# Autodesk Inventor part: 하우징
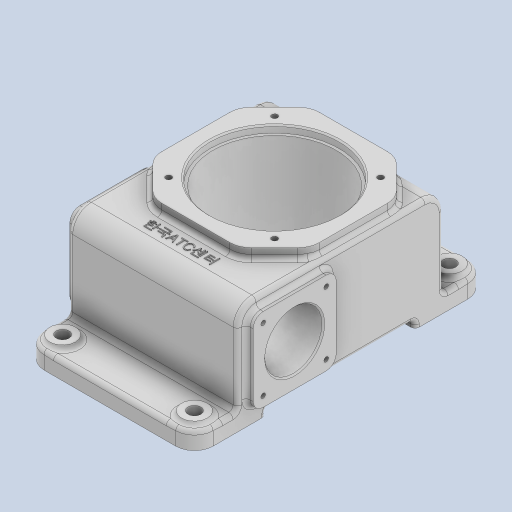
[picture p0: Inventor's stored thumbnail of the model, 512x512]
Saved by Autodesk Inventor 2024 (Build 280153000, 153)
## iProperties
Created: 2026-02
Part Number: 하우징
Material: 일반
Document SubType Name: Modeling
Designer: 2-10
Density: 1 g/cm^3
Appearance: 기본값
Author: 2-10
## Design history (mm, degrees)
sketch "스케치2"
  geometry: L1 (-59, -37.5)-(59, -37.5); L2 (59, -37.5)-(59, 37.5); L3 (59, 37.5)-(-59, 37.5); L4 (-59, 37.5)-(-59, -37.5); L5 (-59, -37.5)-(59, 37.5); L6 (59, -37.5)-(-59, 37.5); 1 further point
  constraints: 12 end point, 2 midpoint, 2 parallel, 1 horizontal, 1 perpendicular
  dimensions: "d4" = 118 distance of L1.start L1.end; "d5" = 75 distance of L1.end L2.end
extrude "돌출2" new body sketch "스케치2" stored distance "d6" = 144; taper "d7" = 0 deg
sketch "스케치3"
  geometry: L1 (118, 0)-(118, -144) reference; L2 (0, 0)-(118, 0) reference; L3 (0, -144)-(0, 0) reference; L4 (118, -144)-(0, -144) reference; L5 (0, 30)-(118, 30); L6 (118, 30)-(118, -174); L7 (118, -174)-(0, -174); L8 (0, -174)-(0, 30); 7 further points
  constraints: 8 end point, 2 midpoint, 2 parallel, 1 horizontal, 1 perpendicular, 1 vertical alignment
  dimensions: "d8" = 204 distance of L5.end L6.end; "d9" = 30 distance between parallel lines of L7 L4; "d10" = 118 distance of L5.start L5.end
extrude "돌출3" join sketch "스케치3" distance "d11" = 12; taper "d12" = 0 deg
fillet "모깎기1" dims "d34" = 13
sketch "스케치4"
  geometry: L1 (4, 30)-(114, 30); L2 (114, 30)-(114, 140); L3 (114, 140)-(4, 140); L4 (4, 140)-(4, 30); L5 (4, 30)-(114, 140); L6 (114, 30)-(4, 140); A1 r 13 centre (105, -17) between (105, -30) and (118, -17) reference; 3 further points
  constraints: 12 end point, 2 midpoint, 2 parallel, 1 horizontal, 1 perpendicular, 1 vertical alignment
  dimensions: "d13" = 110 distance of L2.end L3.end; "d14" = 110 distance of L1.end L2.end; "d51" = 102 vertical distance of A1.centre point (59, 85)
extrude "돌출4" join sketch "스케치4" distance "d15" = 7; taper "d16" = 0 deg
chamfer "모따기1" distance "d17" = 25; stored, may be unused: second distance "d18" = 2, angle "d19" = 45 deg
sketch "스케치5"
  geometry: L1 (4, 115)-(4, 55) reference; C1 r 45 at (59, 85); 2 further points
  constraints: 1 centre point, 1 horizontal alignment, 1 midpoint, 1 vertical alignment
  dimensions: "d52" = 90 diameter of C1
extrude "돌출5" cut sketch "스케치5" distance "d21" = 5; taper "d22" = 0 deg
sketch "스케치6"
  geometry: L1 (39.5, -13)-(-26.5, -13); L2 (39.5, 30)-(-18.5, 30); L3 (-21.5, 27)-(-21.5, 18); L4 (-21.5, 18)-(-15.5, 12); L5 (-15.5, 12)-(-15.5, 7); L6 (-15.5, 7)-(-25, 7); L7 (-26.5, 5.5)-(-26.5, -13); L8 (39.5, 30)-(39.5, -13); L9 (39.5, 32)-(39.5, -58) reference; A1 r 1.5 centre (-25, 5.5) between (-25, 7) and (-26.5, 5.5); A2 r 3 centre (-18.5, 27) between (-18.5, 30) and (-21.5, 27); 4 further points
  constraints: 16 end point, 4 point on circle, 4 point on line, 4 tangent, 3 vertical, 2 centre point, 2 horizontal, 2 perpendicular, 1 coincident, 1 midpoint, 1 vertical alignment
  dimensions: "d24" = 86 diameter of L2 L1; "d25" = 40 diameter of L6 L1; "d26" = 45 deg angle of L1 L4; "d27" = 50 diameter of L4.end L1; "d28" = 6 distance between parallel lines of L5 L3; "d29" = 11 distance between parallel lines of L7 L5; "d30" = 1.5 radius of A1; "d31" = 61 distance of L2.start point (-21.5, 30); "d33" = 3 radius of A2
revolve "회전1" sketch "스케치6" stored, may be unused: angle "d32" = 90 deg
sketch "스케치8"
  geometry: C1 r 9 at (13, 161); C2 r 9 at (105, 161); C3 r 9 at (13, -17); C4 r 9 at (105, -17); A1 r 13 centre (13, 161) between (13, 174) and (0, 161) reference; A2 r 13 centre (105, 161) between (118, 161) and (105, 174) reference; A3 r 13 centre (13, -17) between (0, -17) and (13, -30) reference; A4 r 13 centre (105, -17) between (105, -30) and (118, -17) reference; 1 further point
  constraints: 4 centre point, 4 coincident, 3 equal radius
  dimensions: "d35" = 18 diameter of C1
extrude "돌출6" join sketch "스케치8" distance "d36" = 3; taper "d37" = 0 deg
sketch "스케치9"
  geometry: C1 r 9 at (0, 0) reference; C2 r 9 at (92, 0) reference; C3 r 9 at (0, -178) reference; C4 r 9 at (92, -178) reference; 5 further points
  constraints: 4 coincident
hole "구멍1" sketch "스케치9" at (0, 0), (92, 0), (0, -178), (92, -178) diameter "d38" = 9; stored, may be unused: countersink angle "d42" = 90 deg, drill point angle "d44" = 118 deg; dims "d39" = 6, "d40" = 4, "d41" = 2, "d43" = 8
sketch "스케치10"
  geometry: L1 (-17, -75)-(161, -75) reference; L2 (80, -64)-(138, -64); L3 (138, -64)-(138, -6); L4 (138, -6)-(80, -6); L5 (80, -6)-(80, -64); L6 (80, -64)-(138, -6); L7 (138, -64)-(80, -6); L8 (165.5, -75)-(156.5, -75) reference; L9 (156.5, -60)-(165.5, -60) reference; L10 (29, 7)-(89, 7) reference; 4 further points
  constraints: 12 end point, 4 midpoint, 2 parallel, 1 horizontal, 1 perpendicular
  dimensions: "d45" = 40 distance from line of L1 point (109, -35); "d46" = 58 distance of L3.end L4.end; "d47" = 58 distance of L2.end L3.end; "d50" = 52 horizontal distance of point (109, -35) point (161, -60); "d83" = 50 horizontal distance of point (109, -35) point (59, 7) (derived)
extrude "돌출7" join sketch "스케치10" distance "d53" = 5; taper "d54" = 0 deg
sketch "스케치12"
  geometry: L1 (138, -6)-(80, -6) reference; L2 (80, -6)-(80, -64) reference; C1 r 20 at (109, -35); 3 further points
  constraints: 2 midpoint, 1 centre point, 1 horizontal alignment, 1 vertical alignment
  dimensions: "d55" = 40 diameter of C1
extrude "돌출8" cut sketch "스케치12" extent not by distance; stored distance "d56" = 0; taper "d57" = 0 deg
sketch "스케치13"
  geometry: L1 (-17, -75)-(161, -75) reference; L2 (20, -70)-(124, -70); L3 (124, -70)-(124, -75); L4 (124, -75)-(20, -75); L5 (20, -75)-(20, -70); L6 (174, -75)-(174, -63) reference; L7 (-30, -63)-(-30, -75) reference; 1 further point
  constraints: 8 end point, 2 parallel, 1 horizontal, 1 perpendicular, 1 point on line
  dimensions: "d58" = 50 distance between parallel lines of L3 L6; "d59" = 50 distance between parallel lines of L5 L7; "d60" = 5 distance between parallel lines of L4 L2
extrude "돌출9" cut sketch "스케치13" extent not by distance; stored distance "d61" = 0; taper "d62" = 0 deg
sketch "스케치14"
  geometry: L1 (87, -57)-(131, -57); L2 (131, -57)-(131, -13); L3 (131, -13)-(87, -13); L4 (87, -13)-(87, -57); L5 (87, -57)-(131, -13); L6 (131, -57)-(87, -13); C1 r 20 at (109, -35) reference; 1 further point
  constraints: 12 end point, 2 midpoint, 2 parallel, 1 horizontal, 1 perpendicular
  dimensions: "d63" = 44 distance of L2.end L3.end; "d64" = 44 distance of L1.end L2.end
hole "구멍2" sketch "스케치14" at (87, -57), (131, -13), (131, -57), (87, -13) diameter "d65" = 3.242; stored, may be unused: countersink angle "d69" = 90 deg, drill point angle "d71" = 118 deg; dims "d66" = 8, "d67" = 4, "d68" = 2, "d70" = 10
fillet "모깎기4" dims "d84" = 7
sketch "스케치15"
  geometry: L1 (22, 122)-(96, 122); L2 (96, 122)-(96, 48); L3 (96, 48)-(22, 48); L4 (22, 48)-(22, 122); L5 (22, 122)-(96, 48); L6 (96, 122)-(22, 48); C1 r 45 at (59, 85) reference; 1 further point
  constraints: 12 end point, 2 midpoint, 2 parallel, 1 horizontal, 1 perpendicular
  dimensions: "d72" = 74 distance of L1.end L2.end; "d73" = 74 distance of L2.end L3.end
hole "구멍3" sketch "스케치15" at (96, 122), (96, 48), (22, 48), (22, 122) diameter "d74" = 4.134; stored, may be unused: countersink angle "d78" = 90 deg, drill point angle "d80" = 118 deg; dims "d75" = 10, "d76" = 4, "d77" = 2, "d79" = 12
fillet "모깎기2" dims "d81" = 13
fillet "모깎기5" dims "d85" = 3
fillet "모깎기6" dims "d86" = 3
fillet "모깎기7" dims "d87" = 3
chamfer "모따기2" distance "d88" = 1; stored, may be unused: second distance "d89" = 2, angle "d90" = 45 deg
node "작업 평면1"
sketch "스케치17"
  geometry: C1 r 46 at (56, 72) reference; 2 further points
  constraints: 1 vertical alignment, 1 other
  dimensions: "d92" = 65 distance of point (56, 7) C1.centre
feature "엠보싱1" sketch "스케치17" dims "d4" = 118, "d5" = 75, "d11" = 12, "d12" = 0, "d93" = 0.5, "d94" = 0
fillet "모깎기9" dims "d96" = 15
fillet "모깎기10" dims "d97" = 3
node "솔리드2"
mirror "미러2"
node "투영된 루프1"
feature "A9D066F2-1C7D-4E18-AEED-F7BC21143FA4" dims "d65" = 3.242, "d66" = 8, "d67" = 4, "d68" = 2, "d69" = 90 deg, "d70" = 10, "d71" = 118 deg
other parameters: "d91" = 46.75
